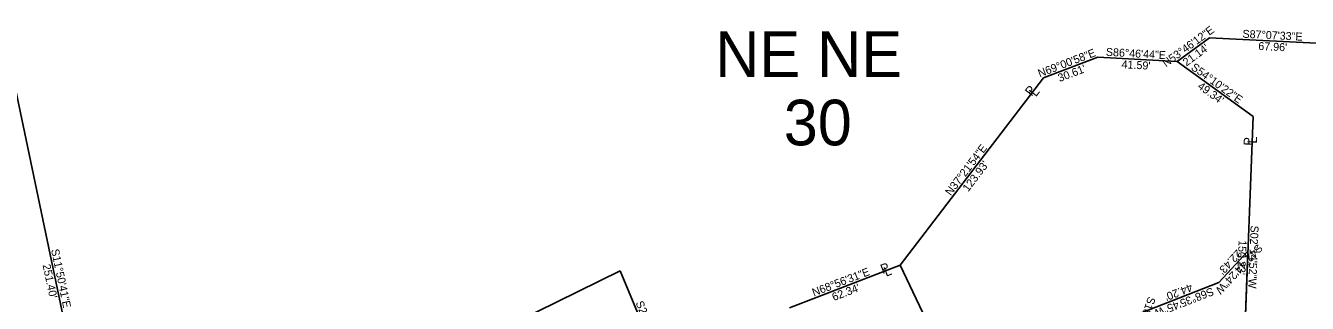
# Model space of a CAD drawing. Extents: x 1145508 to 2262867, y -3126236 to 2021677.
# Drawn here: x 1151042 to 1151715, y 2020512 to 2020658 of the extents above; entities that cross this region are included whole.
import ezdxf

# ---------------------------------------------------------------- set-up
doc = ezdxf.new("R2010")
doc.units = 0
for name, color, linetype in [('DSN_DRFT_Guideline-No-Plot', 7, 'Continuous'), ('DSN_ROW_Annotation', 7, 'Continuous'), ('DSN_ROW_Line', 7, 'Continuous'), ('DSN_ROW_Prop-Line', 7, 'Continuous'), ('DSN_ROW_Prop-Line-Annotation', 7, 'Continuous'), ('E_Const Align', 7, 'Continuous'), ('SHET_Annotations', 7, 'Continuous')]:
    doc.layers.add(name, color=color, linetype=linetype)

msp = doc.modelspace()

# ---------------------------------------------------------------- linework, layer by layer
at = {"layer": 'DSN_DRFT_Guideline-No-Plot'}
msp.add_line((1151683.89, 2020538.97), (1151680.79, 2020459.79), dxfattribs=at)
at = {"layer": 'DSN_ROW_Line'}
for p, q in [((1151683.89, 2020538.97), (1151668.67, 2020522.5)), ((1151668.67, 2020522.5), (1151627.52, 2020506.37))]:
    msp.add_line(p, q, dxfattribs=at)
at = {"layer": 'DSN_ROW_Prop-Line'}
for p, q in [((1151646.66, 2020638.78), (1151663.71, 2020651.28)), ((1151663.71, 2020651.28), (1151731.59, 2020647.87)), ((1151032.27, 2020646.17), (1151083.87, 2020400.12)), ((1151576.56, 2020630.16), (1151605.14, 2020641.12)), ((1151605.14, 2020641.12), (1151646.66, 2020638.79)), ((1151646.66, 2020638.79), (1151686.67, 2020609.9)), ((1151501.35, 2020531.67), (1151576.56, 2020630.16)), ((1151686.68, 2020609.91), (1151680.79, 2020459.79)), ((1151443.17, 2020509.27), (1151501.35, 2020531.67)), ((1151501.35, 2020531.67), (1151537.63, 2020455.5)), ((1151231.91, 2020468.63), (1151354.39, 2020528.69)), ((1151354.39, 2020528.69), (1151381.42, 2020463.37))]:
    msp.add_line(p, q, dxfattribs=at)
at = {"layer": 'E_Const Align'}
msp.add_arc((1152722.75, 2017772.83), 2864.79, 104.86102, 121.82944, dxfattribs=at)
msp.add_arc((1152722.75, 2017772.83), 2864.79, 104.86102, 121.82944, dxfattribs=at)

# ---------------------------------------------------------------- texts
at = {"layer": 'DSN_DRFT_Guideline-No-Plot'}
for rotation, p in [(8.89819, (1151605.11, 2020641.05)), (340.49844, (1151646.6, 2020638.75)), (36.80884, (1151576.55, 2020630.07)), (295.97101, (1151686.62, 2020609.92)), (337.50604, (1151683.84, 2020538.94)), (84.0507, (1151501.39, 2020531.62)), (34.33204, (1151668.67, 2020522.44))]:
    msp.add_text('+', height=0.1, rotation=rotation, dxfattribs=at).set_placement(p)
at = {"layer": 'DSN_ROW_Annotation'}
for s, rotation, p in [('N53°46\'12"E', 36.22993, (1151640.89, 2020635.68)), ('S87°07\'33"E', 357.1258, (1151680.95, 2020651.31)), ('N69°00\'58"E', 20.98393, (1151574.6, 2020630.37)), ('S86°46\'44"E', 356.77887, (1151609.21, 2020641.79)), ("21.14'", 36.22993, (1151651.62, 2020636.1)), ("67.96'", 357.1258, (1151689.25, 2020644.89)), ("30.61'", 20.98393, (1151585.06, 2020627.96)), ("41.59'", 356.77887, (1151617.47, 2020635.32)), ('S54°10\'22"E', 324.17281, (1151653.6, 2020634.89)), ("49.34'", 324.17281, (1151657.07, 2020624.98)), ('N37°21\'54"E', 52.63514, (1151527.88, 2020567.9)), ("123.93'", 52.63514, (1151537.02, 2020569.98)), ('S02°14\'52"W', 267.75219, (1151685.33, 2020552.57)), ('S42°44\'24"W', 227.25989, (1151689, 2020543.17)), ("150.23'", 267.75219, (1151679.02, 2020544.9)), ('S11°50\'41"E', 281.84475, (1151055.51, 2020539.74)), ("22.43'", 227.25989, (1151678.07, 2020540.18)), ("251.40'", 281.84475, (1151051.06, 2020531.75)), ('N68°56\'31"E', 21.05801, (1151456.02, 2020515.18)), ("62.34'", 21.05801, (1151466.49, 2020512.78)), ('S68°35\'45"W', 201.40419, (1151664.97, 2020520.08)), ("44.20'", 201.40419, (1151653.82, 2020522.16)), ('S22°28\'45"E', 292.47918, (1151362.33, 2020511.86)), ('S18°35\'30"W', 251.40839, (1151631.52, 2020515.44))]:
    msp.add_text(s, height=4.2, rotation=rotation, dxfattribs=at).set_placement(p)
at = {"layer": 'DSN_ROW_Prop-Line-Annotation'}
for s, rotation, p in [('P', 52.17436, (1151570.33, 2020620.18)), ('L', 52.17436, (1151572.56, 2020619.93)), ('P', 87.88564, (1151686.57, 2020594.44)), ('L', 87.88564, (1151688.53, 2020595.54)), ('P', 20.7432, (1151492.12, 2020526.95)), ('L', 20.7432, (1151493.89, 2020525.57))]:
    msp.add_text(s, height=5, rotation=rotation, dxfattribs=at).set_placement(p)
at = {"layer": 'SHET_Annotations'}
for s, p in [('NE NE', (1151404.21, 2020630.69)), ('30', (1151440.21, 2020594.69))]:
    msp.add_text(s, height=24, dxfattribs=at).set_placement(p)

doc.saveas('drawing.dxf')
